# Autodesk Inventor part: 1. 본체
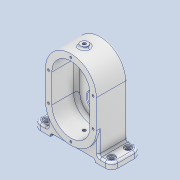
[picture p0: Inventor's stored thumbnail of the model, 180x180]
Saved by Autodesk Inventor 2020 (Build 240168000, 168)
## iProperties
Created: 2021-05
Part Number: 1. 본체
Material: 알루미늄 6061
Document SubType Name: Modeling
Designer: Owner
Density: 2.7 g/cm^3
Appearance: 알루미늄 - 평지
Author: Owner
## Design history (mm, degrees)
sketch "스케치4"
  geometry: L1 (0, -22.5)-(0, 22.5); L2 (40, -22.5)-(40, 22.5); L3 (-40, 22.5)-(-40, -22.5); A1 r 40 centre (0, -22.5) between (-40, -22.5) and (40, -22.5); A2 r 40 centre (0, 22.5) between (40, 22.5) and (-40, 22.5); 2 further points
  constraints: 8 end point, 4 point on circle, 4 tangent, 2 centre point, 1 coincident, 1 midpoint, 1 parallel, 1 vertical
  dimensions: "d15" = 40 radius of A2; "d16" = 45 distance of L3.start L3.end
extrude "돌출4" new body sketch "스케치4" stored distance "d17" = 49; taper "d18" = 0 deg
feature "쉘1" dims "d19" = 10
node "작업 평면1"
sketch "스케치5"
  geometry: L1 (-61, 24.5)-(61, 24.5); L2 (61, 24.5)-(61, -21.5); L3 (61, -21.5)-(-61, -21.5); L4 (-61, -21.5)-(-61, 24.5); L5 (0, 60.783)-(0, -54.984); L6 (90.887, 0)-(-105.505, 0); 1 further point
  constraints: 12 end point, 2 horizontal, 2 parallel, 2 point on line, 1 perpendicular, 1 vertical
  dimensions: "d29" = 122 distance of L1.start L1.end; "d30" = 46 distance of L1.end L2.end; "d31" = 122 diameter of L4 L5 (= d29); "d32" = 49 diameter of L1 L6
extrude "돌출5" join sketch "스케치5" distance "d23" = 10; taper "d24" = 0 deg
sketch "스케치7"
  geometry: L1 (35, 24.5)-(-35, 24.5); L2 (-35, 24.5)-(-35, -21.5); L3 (-35, -21.5)-(35, -21.5); L4 (35, -21.5)-(35, 24.5); L5 (0, 66.655)-(0, -84.262); L6 (-61, 24.5)-(61, 24.5) reference; 1 further point
  constraints: 10 end point, 2 parallel, 1 collinear, 1 horizontal, 1 perpendicular, 1 point on line, 1 vertical
  dimensions: "d33" = 70 distance of L3.end L2.end; "d34" = 46 distance of L2.end L1.end; "d35" = 70 diameter of L4 L5 (= d33)
extrude "돌출7" cut sketch "스케치7" distance "d36" = 5; taper "d37" = 0 deg
node "작업 평면2"
sketch "스케치8"
  geometry: L1 (-40, -24.5)-(40, -24.5) reference; C1 r 6 at (0, -3.5)
  constraints: 1 centre point
  dimensions: "d140" = 21 distance from line of C1.centre L1; "d141" = 12 diameter of C1
extrude "돌출8" join sketch "스케치8" stored distance "d40" = 5; taper "d41" = 0 deg
sketch "스케치20"
  geometry: 2 further points
hole "구멍5" sketch "스케치20" at (0, 0) diameter "d142" = 4.917; stored, may be unused: countersink angle "d146" = 90 deg, drill point angle "d148" = 118 deg; dims "d143" = 12, "d144" = 12, "d145" = 1, "d147" = 17.1
sketch "스케치9"
  geometry: L1 (0, 22.5)-(0, -22.5); L2 (26, 22.5)-(26, -22.5); L3 (-26, -22.5)-(-26, 22.5); L4 (26, 7.5)-(-26, 7.5); A1 r 26 centre (0, 22.5) between (26, 22.5) and (-26, 22.5); A2 r 26 centre (0, -22.5) between (-26, -22.5) and (26, -22.5); 1 further point
  constraints: 10 end point, 4 point on circle, 4 tangent, 2 centre point, 2 point on line, 1 horizontal, 1 midpoint, 1 parallel, 1 vertical
  dimensions: "d49" = 52 distance between parallel lines of L3 L2; "d50" = 45 distance of L1.start L1.end; "d51" = 30 distance from line of L4 L1.end
extrude "돌출9" join sketch "스케치9" distance "d52" = 8; taper "d53" = 0 deg
sketch "스케치10"
  geometry: L1 (93.828, 22.5)-(-161.431, 22.5); L2 (61, 69.5)-(35, 69.5) reference; L3 (0, 93.764)-(0, -111.085); L4 (26, 7.5)-(26, -22.5) reference; L5 (26, 7.5)-(26, 22.5); L6 (-26, -22.5)-(-26, 7.5) reference; L7 (-26, 7.5)-(-26, 22.5); C1 r 14 at (0, -22.5); C2 r 11 at (0, -22.5); A1 r 26 centre (0, -22.5) between (-26, -22.5) and (26, -22.5) reference; A2 r 26 centre (0, 22.5) between (26, 22.5) and (-26, 22.5); 1 further point
  constraints: 8 end point, 3 centre point, 3 point on line, 2 coincident, 2 point on circle, 2 tangent, 1 collinear, 1 horizontal, 1 perpendicular, 1 vertical
  dimensions: "d54" = 28 diameter of C1; "d55" = 22 diameter of C2; "d63" = 47 distance between parallel lines of L1 L2
extrude "돌출10" cut sketch "스케치10" distance "d56" = 4; taper "d57" = 0 deg
extrude "돌출11" cut sketch "스케치10" distance "d58" = 205.5; taper "d59" = 0 deg
sketch "스케치11"
  geometry: C1 r 14 at (0, 0); C2 r 11 at (0, 0) reference; 1 further point
  constraints: 1 centre point
  dimensions: "d60" = 28 diameter of C1
extrude "돌출12" cut sketch "스케치11" distance "d61" = 8; taper "d62" = 0 deg
sketch "스케치12"
  geometry: L1 (0, 0)-(0, 116.266); L2 (96.451, 22.5)-(-125.299, 22.5); L3 (-35, 69.5)-(-61, 69.5) reference; L4 (26, 7.5)-(26, -22.5) reference; L5 (26, 7.5)-(26, 22.5); L6 (-26, 7.5)-(26, 7.5) reference; L7 (-26, 7.5)-(-26, 22.5); A1 r 26 centre (0, 22.5) between (26, 22.5) and (-26, 22.5)
  constraints: 8 end point, 2 perpendicular, 2 point on circle, 2 point on line, 2 tangent, 1 centre point, 1 horizontal, 1 vertical
  dimensions: "d64" = 47 distance between parallel lines of L2 L3
extrude "돌출13" join sketch "스케치12" distance "d65" = 11; taper "d66" = 0 deg
sketch "스케치13"
  geometry: L1 (35, -92)-(61, -92) reference; L2 (0, -116.743)-(0, 80.334); L3 (-83.569, -45)-(143.447, -45); C1 r 14 at (0, -45); C2 r 11 at (0, -45); 1 further point
  constraints: 4 end point, 3 point on line, 2 centre point, 1 coincident, 1 horizontal, 1 vertical
  dimensions: "d68" = 47 distance between parallel lines of L3 L1; "d69" = 28 diameter of C1; "d70" = 22 diameter of C2
extrude "돌출14" cut sketch "스케치13" distance "d71" = 8; taper "d72" = 0 deg
extrude "돌출15" cut sketch "스케치13" distance "d73" = 12; taper "d74" = 0 deg
sketch "스케치14"
  geometry: L1 (-40, -24.5)-(40, -24.5) reference; 2 further points
  dimensions: "d75" = 21 distance from line of point (0, -3.5) L1
hole "구멍2" sketch "스케치14" at (0, -3.5) diameter "d76" = 4.917; stored, may be unused: countersink angle "d80" = 90 deg, drill point angle "d82" = 118 deg; dims "d77" = 16.25, "d78" = 12, "d79" = 1, "d81" = 16.75
sketch "스케치15"
  geometry: L1 (-40, 22.5)-(-40, 59.5); L2 (40, -22.5)-(40, 22.5) reference; L3 (40, 22.5)-(40, 59.5); L4 (61, 59.5)-(15.199, 59.5) reference; L5 (-15.199, 59.5)-(-61, 59.5) reference; A1 r 40 centre (0, 22.5) between (-15.199, 59.5) and (-40, 22.5) reference; A2 r 40 centre (0, 22.5) between (40, 22.5) and (15.199, 59.5) reference; 1 further point
  constraints: 4 end point, 2 vertical, 1 tangent
extrude "돌출16" join sketch "스케치15" distance "d83" = 46; taper "d84" = 0 deg
sketch "스케치16"
  geometry: L1 (34.832, 22.5)-(-35.168, 22.5); L2 (0, 110.946)-(0, -79.008); A1 r 35 centre (-0.168, 22.5) between (34.832, 22.5) and (-35.168, 22.5); 3 further points
  constraints: 4 end point, 3 point on circle, 2 point on line, 1 centre point, 1 coincident, 1 horizontal, 1 midpoint, 1 vertical
  dimensions: "d86" = 70 diameter of A1; "d87" = 22.5 vertical distance of point (0, 0) A1.centre; "d88" = 57.4996 distance of point (0, 0) point (0, 57.5)
hole "구멍3" sketch "스케치16" at (-35.168, 22.5), (34.832, 22.5), (0, 57.5) diameter "d89" = 3.242; stored, may be unused: countersink angle "d93" = 90 deg, drill point angle "d95" = 118 deg; dims "d90" = 8, "d91" = 12, "d92" = 1, "d94" = 10
sketch "스케치17"
  geometry: L1 (61, 24.5)-(40, 24.5) reference; L2 (61, -21.5)-(61, 24.5) reference; L3 (40, -21.5)-(61, -21.5) reference; C1 r 5.5 at (51, 14.5); C2 r 3.3 at (51, 14.5); C3 r 5.5 at (51, -11.5); C4 r 3.3 at (51, -11.5); 1 further point
  constraints: 4 centre point, 2 coincident, 1 vertical alignment
  dimensions: "d96" = 11 diameter of C1; "d97" = 6.6 diameter of C2; "d98" = 11 diameter of C3; "d99" = 6.6 diameter of C4; "d101" = 10 distance from line of C1.centre L1; "d102" = 10 distance from line of L2 C1.centre; "d105" = 10 distance from line of C3.centre L3
fillet "모깎기1" dims "d100" = 10
extrude "돌출17" cut sketch "스케치17" distance "d106" = 46; taper "d107" = 0 deg
extrude "돌출18" cut sketch "스케치17" distance "d108" = 2; taper "d109" = 0 deg
sketch "스케치18"
  geometry: L1 (-59.091, -22.5)-(67.493, -22.5); L2 (0, 82.616)-(0, -92.417); L3 (0, -22.5)-(-72.7, 19.474); L4 (0, -22.5)-(60.116, 12.208); A1 r 20 centre (0, -22.5) between (0, -42.5) and (-17.321, -12.5); 2 further points
  constraints: 8 end point, 5 point on line, 3 point on circle, 1 centre point, 1 horizontal, 1 vertical
  dimensions: "d110" = 40 diameter of A1; "d111" = 120 deg angle of L3 L2; "d112" = 120 deg angle of L4 L3
hole "구멍4" sketch "스케치18" at (0, -42.5), (-17.321, -12.5), (17.321, -12.5) diameter "d113" = 3.242; stored, may be unused: countersink angle "d117" = 90 deg, drill point angle "d119" = 118 deg; dims "d114" = 8, "d115" = 12, "d116" = 1, "d118" = 10
sketch "스케치19"
  geometry: L1 (40, 59.5)-(-40, 59.5); L2 (51, 69.5)-(35, 69.5) reference; L3 (-40, 59.5)-(-40, -22.5) reference; L4 (40, -22.5)-(40, 59.5) reference; 1 further point
  constraints: 2 end point, 2 horizontal, 2 point on line
  dimensions: "d120" = 10 distance between parallel lines of L1 L2
extrude "돌출19" join sketch "스케치19" distance "d121" = 0.5; taper "d122" = 0 deg
fillet "모깎기2" dims "d123" = 5
fillet "모깎기3" dims "d124" = 0.3
fillet "모깎기4" dims "d125" = 0.3
chamfer "모따기1" distance "d126" = 1; stored, may be unused: second distance "d127" = 2, angle "d128" = 45 deg
chamfer "모따기2" distance "d129" = 1; stored, may be unused: second distance "d130" = 2, angle "d131" = 45 deg
fillet "모깎기5" dims "d132" = 3
fillet "모깎기7" dims "d134" = 3
fillet "모깎기8" dims "d135" = 3
fillet "모깎기10" dims "d137" = 3
fillet "모깎기11" dims "d138" = 3
fillet "모깎기13" dims "d149" = 3
node "솔리드2"
mirror "미러1"
mirror "미러2"
feature "A9D066F2-1C7D-4E18-AEED-F7BC21143FA4" dims "d142" = 4.917, "d143" = 12, "d144" = 12, "d145" = 1, "d146" = 90 deg, "d147" = 17.1, "d148" = 118 deg
other parameters: "d20" = -69.5, "d38" = 65.5
